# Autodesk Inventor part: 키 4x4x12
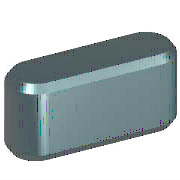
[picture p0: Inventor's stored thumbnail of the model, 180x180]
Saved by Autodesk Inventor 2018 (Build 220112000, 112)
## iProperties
IsCustomPart: 1
Created: 2012-02
Part Number: 키 4x4x12
Material: 강철, 연강
Description: 키 및 해당 키홈
Document SubType Name: Modeling
Standard: KS B 1311
Designer: mduedu
Standards Organization: KS
Language: ko-KR
Size Designation: 4 x 4 x 12
Categories: <MemberInstance><Categories><Category DisplayName="샤프트 부품" InternalName="7f7aeb1f-a693-4053-b835-cee3144e0d98" Mnemonic="SHFT"><Category DisplayName="키" Interna
Density: 7.85 g/cm^3
Appearance: 노란색
Mass: 1.38563 g
Surface Area: 1.94869 cm^2
Volume: 0.176513 cm^3
Author: mduedu
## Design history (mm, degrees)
workplane "Work Plane1"
workplane "Work Plane2"
sketch "스케치1"
  geometry: L1 (2, 2)-(10, 2); L2 (10, -2)-(2, -2); L3 (0, 9.4)-(0, -7.4) reference; L4 (-5, 0)-(30, 0) reference; L5 (12, 0)-(12, 7); A1 r 2 centre (2, 0) between (2, 2) and (2, -2); A2 r 2 centre (10, 0) between (10, -2) and (10, 2)
  constraints: 6 end point, 5 point on circle, 4 tangent, 3 point on line, 2 centre point, 1 horizontal, 1 parallel, 1 perpendicular
  dimensions: "d0" = 2 radius of A1 (= 0.5 x PB); "d13" = 2 radius of A2 (= 0.5 x PB); "d14" = 12 distance between parallel lines of L5 L3 (= NLG)
extrude "본체1" new body sketch "스케치1" taper "d3" = 0 deg; stored distance "d4" = 10
workplane "Work Plane3"
body "Solid1"
chamfer "모따기1" distance "d8" = 0.25 (= PHH); stored, may be unused: second distance "d9" = 0.25 (= PHH), angle "d15" = 45 deg
other parameters: "d1" = -2.5 (= -PNT), "d2" = 1.5 (= PH - PNT), "NLG" = 12 [user parameter; used in 3 equation terms], "PB" = 4 [user parameter; used in 2 equation terms], "PNT" = 2.5 [user parameter; used in 2 equation terms], "PH" = 4 [user parameter; used in 1 equation term], "PHH" = 0.25 [user parameter; used in 2 equation terms], "d10" = 0, "d16" = 0, "d17" = 0, "d18" = 0, "PLB2" = 12 (= NLG) [user parameter], "WDMAX" = 12 [user parameter], "PLB1" = 12 (= NLG) [user parameter], "RR" = 0.08 [user parameter], "PUEB" = 1.8 [user parameter]
